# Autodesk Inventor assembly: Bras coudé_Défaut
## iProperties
Shininess: 64.0
Length Units: 11269
Angle Units: 11279
Time Units: 11290
Mass Units: 11283
Length Display Precision: 3
Angle Display Precision: 2
Compacted: True
Created: 2006-11
Part Number: Bras coudé_Défaut
Document SubType Name: Assembly
Designer: profs_sti
Density: 0.0
Volumn: 0.0
Area: 0.0
PropertySet Name: Model Information
Control State: 0
Master: False
Checked Out: False
Author: profs_sti
